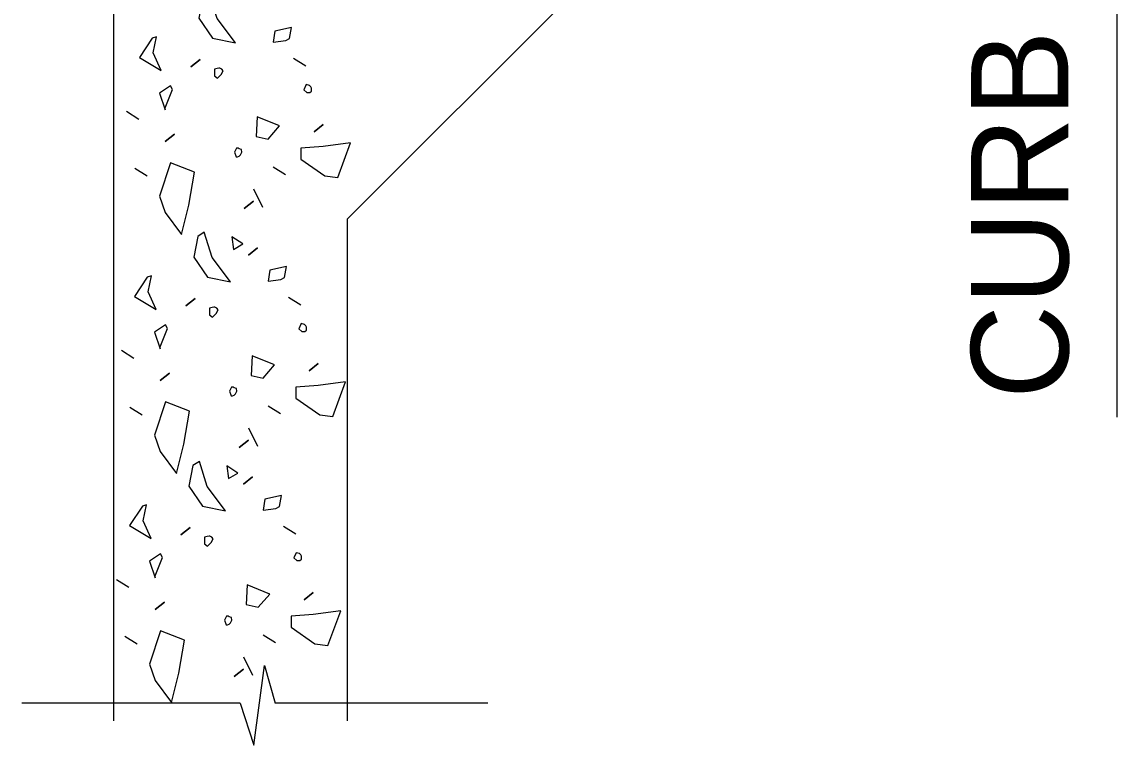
# Model space of a CAD drawing. Extents: x 0 to 90.7, y 0 to 62.8.
# Drawn here: x 13.511 to 18.201, y 31.613 to 34.711 of the extents above; entities that cross this region are included whole.
import ezdxf

# ---------------------------------------------------------------- set-up
doc = ezdxf.new("R2010")
doc.units = 0
for name, color, linetype in [('BRDG_ANNO_General-Notes', 7, 'Continuous'), ('BRDG_BASE_Obj-Line', 7, 'Continuous'), ('BRDG_BASE_Pattern', 7, 'Continuous')]:
    doc.layers.add(name, color=color, linetype=linetype)

msp = doc.modelspace()

# ---------------------------------------------------------------- linework, layer by layer
at = {"layer": 'BRDG_ANNO_General-Notes'}
msp.add_line((18.2006, 33.018), (18.2006, 35.8655), dxfattribs=at)
at = {"layer": 'BRDG_BASE_Obj-Line'}
for p, q in [((13.9034, 35.8655), (13.9034, 31.7159)), ((14.9034, 33.8655), (15.9034, 34.8655)), ((14.9034, 33.8655), (14.9034, 31.7159)), ((14.504, 31.6126), (14.5492, 31.9534)), ((14.5492, 31.9534), (14.5952, 31.7924)), ((14.4456, 31.7924), (13.511, 31.7924)), ((14.4456, 31.7924), (14.504, 31.6126)), ((15.5062, 31.7924), (14.5952, 31.7924))]:
    msp.add_line(p, q, dxfattribs=at)
at = {"layer": 'BRDG_BASE_Pattern'}
for p, q in [((14.6736, 34.5564), (14.7265, 34.5231)), ((13.9594, 34.328), (14.0123, 34.2948)), ((13.9948, 34.0844), (14.0477, 34.0511)), ((14.5871, 34.0902), (14.6399, 34.0569)), ((14.5024, 33.9958), (14.5417, 33.9172)), ((14.6522, 33.5324), (14.7051, 33.4992)), ((13.9381, 33.3041), (13.9909, 33.2709)), ((14.5658, 33.0662), (14.6186, 33.033)), ((13.9735, 33.0605), (14.0263, 33.0272)), ((14.4811, 32.9719), (14.5204, 32.8933)), ((14.6309, 32.5511), (14.6838, 32.5179)), ((13.9168, 32.3228), (13.9696, 32.2896)), ((13.9522, 32.0792), (14.005, 32.0459)), ((14.5445, 32.0849), (14.5973, 32.0517)), ((14.4598, 31.9906), (14.4991, 31.912))]:
    msp.add_line(p, q, dxfattribs=at)
for points in [[(14.286, 34.816), (14.2684, 34.7274), (14.3274, 34.641), (14.4256, 34.6214), (14.347, 34.7257), (14.3135, 34.8335)], [(14.5942, 34.6714), (14.5864, 34.6242), (14.6415, 34.632), (14.6571, 34.6399), (14.665, 34.6871)], [(14.0695, 34.641), (14.0145, 34.5584), (14.107, 34.5031), (14.0734, 34.5781), (14.0873, 34.6467)], [(14.2348, 34.5192), (14.2742, 34.5506)], [(14.3353, 34.5092), (14.3353, 34.4795), (14.3488, 34.4699), (14.3528, 34.4738), (14.3645, 34.4856), (14.3724, 34.5013), (14.3667, 34.5092), (14.3588, 34.5131), (14.3549, 34.5131), (14.347, 34.5109)], [(14.1002, 34.4059), (14.1241, 34.3348), (14.1241, 34.3427), (14.1556, 34.4217), (14.1477, 34.4374)], [(14.7286, 34.4423), (14.7186, 34.4206), (14.7304, 34.4088), (14.7443, 34.4088), (14.7504, 34.4148), (14.7504, 34.4267), (14.7482, 34.4324), (14.7422, 34.4384)], [(14.5182, 34.3045), (14.5142, 34.2202), (14.5654, 34.2083), (14.6146, 34.2652)], [(14.7622, 34.2398), (14.8015, 34.2713)], [(14.1248, 34.1984), (14.1642, 34.2298)], [(14.8004, 34.1777), (14.706, 34.1698), (14.706, 34.1226), (14.8082, 34.0519), (14.8636, 34.044), (14.9186, 34.1933)], [(14.4218, 34.153), (14.4278, 34.1333), (14.4335, 34.1333), (14.4414, 34.1355), (14.4474, 34.1412), (14.4531, 34.153), (14.4514, 34.1647), (14.4414, 34.1669), (14.4374, 34.1708), (14.4296, 34.1708)], [(14.1477, 34.1069), (14.1002, 33.9651), (14.1241, 33.8944), (14.1949, 33.8001), (14.2263, 33.9258), (14.2498, 34.0676)], [(14.4632, 33.9111), (14.5024, 33.9426)], [(14.2646, 33.7921), (14.2471, 33.7035), (14.306, 33.6171), (14.4043, 33.5974), (14.3257, 33.7018), (14.2921, 33.8096)], [(14.4093, 33.791), (14.4172, 33.736), (14.4568, 33.7596)], [(14.4811, 33.7114), (14.5204, 33.7428)], [(14.5729, 33.6474), (14.565, 33.6003), (14.6201, 33.6081), (14.6358, 33.616), (14.6436, 33.6632)], [(14.0481, 33.6171), (13.9931, 33.5345), (14.0856, 33.4792), (14.0521, 33.5542), (14.066, 33.6228)], [(14.2135, 33.4953), (14.2529, 33.5267)], [(14.3139, 33.4853), (14.3139, 33.4556), (14.3274, 33.446), (14.3314, 33.4499), (14.3432, 33.4617), (14.351, 33.4774), (14.3453, 33.4853), (14.3374, 33.4892), (14.3335, 33.4892), (14.3257, 33.487)], [(14.0789, 33.382), (14.1028, 33.3109), (14.1028, 33.3188), (14.1343, 33.3978), (14.1264, 33.4135)], [(14.7072, 33.4184), (14.6972, 33.3967), (14.709, 33.3849), (14.723, 33.3849), (14.7291, 33.3909), (14.7291, 33.4028), (14.7269, 33.4085), (14.7208, 33.4145)], [(14.4968, 33.2806), (14.4929, 33.1962), (14.544, 33.1844), (14.5933, 33.2413)], [(14.1035, 33.1745), (14.1428, 33.2059)], [(14.7408, 33.2159), (14.7801, 33.2473)], [(14.7791, 33.1538), (14.6847, 33.1459), (14.6847, 33.0987), (14.7869, 33.028), (14.8423, 33.0201), (14.8973, 33.1694)], [(14.4004, 33.1291), (14.4065, 33.1094), (14.4121, 33.1094), (14.4201, 33.1116), (14.4261, 33.1173), (14.4318, 33.1291), (14.43, 33.1408), (14.4201, 33.143), (14.4161, 33.1469), (14.4082, 33.1469)], [(14.1264, 33.083), (14.0789, 32.9412), (14.1028, 32.8705), (14.1735, 32.7761), (14.2049, 32.9019), (14.2285, 33.0437)], [(14.4418, 32.8872), (14.4811, 32.9187)], [(14.2433, 32.8108), (14.2258, 32.7222), (14.2847, 32.6358), (14.383, 32.6161), (14.3044, 32.7205), (14.2708, 32.8283)], [(14.388, 32.8097), (14.3959, 32.7547), (14.4355, 32.7783)], [(14.4598, 32.7301), (14.4991, 32.7615)], [(14.0268, 32.6358), (13.9718, 32.5532), (14.0643, 32.4979), (14.0308, 32.5729), (14.0447, 32.6415)], [(14.5516, 32.6661), (14.5437, 32.619), (14.5988, 32.6268), (14.6145, 32.6347), (14.6223, 32.6819)], [(14.1922, 32.514), (14.2316, 32.5454)], [(14.2926, 32.504), (14.2926, 32.4743), (14.3061, 32.4647), (14.3101, 32.4686), (14.3219, 32.4804), (14.3297, 32.4961), (14.324, 32.504), (14.3161, 32.5079), (14.3122, 32.5079), (14.3044, 32.5057)], [(14.0576, 32.4007), (14.0815, 32.3296), (14.0815, 32.3374), (14.113, 32.4165), (14.1051, 32.4322)], [(14.6859, 32.4371), (14.6759, 32.4154), (14.6877, 32.4036), (14.7017, 32.4036), (14.7078, 32.4096), (14.7078, 32.4215), (14.7056, 32.4272), (14.6995, 32.4332)], [(14.4755, 32.2993), (14.4716, 32.2149), (14.5227, 32.2031), (14.572, 32.26)], [(14.7195, 32.2346), (14.7588, 32.266)], [(14.0822, 32.1932), (14.1215, 32.2246)], [(14.7578, 32.1724), (14.6634, 32.1646), (14.6634, 32.1174), (14.7656, 32.0467), (14.821, 32.0388), (14.876, 32.1881)], [(14.3791, 32.1478), (14.3852, 32.1281), (14.3908, 32.1281), (14.3987, 32.1303), (14.4048, 32.136), (14.4105, 32.1478), (14.4087, 32.1595), (14.3987, 32.1617), (14.3948, 32.1656), (14.3869, 32.1656)], [(14.1051, 32.1017), (14.0576, 31.9599), (14.0815, 31.8892), (14.1522, 31.7948), (14.1836, 31.9206), (14.2072, 32.0624)], [(14.4205, 31.9059), (14.4598, 31.9374)]]:
    msp.add_lwpolyline(points, close=True, dxfattribs=at)

# ---------------------------------------------------------------- texts
at = {"layer": 'BRDG_ANNO_General-Notes'}
msp.add_text('CURB', height=0.41667, rotation=90, dxfattribs=at).set_placement((17.992, 33.0957))

doc.saveas('drawing.dxf')
